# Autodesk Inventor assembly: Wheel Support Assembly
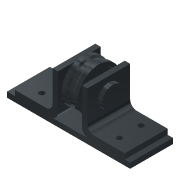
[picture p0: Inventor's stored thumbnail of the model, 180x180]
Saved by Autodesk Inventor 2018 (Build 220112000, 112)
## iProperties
Created: 2016-08
Part Number: Wheel Support Assembly
Document SubType Name: Assembly
Designer: Sandeep
Author: Sandeep
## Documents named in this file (5)
- E:\_Deepak\Inventor\Autodesk Inventor_2017_Project\Resources\Inventor_2018_tut\c15_Inv_tut_2018\c15_tut03_inv\Wheel Support Assembly.iam
- E:\_Deepak\Inventor\Autodesk Inventor_2017_Project\Resources\Inventor_2017_tut\c15_Inv_tut_2017\ch15_tut03\base.ipt
- E:\_Deepak\Inventor\Autodesk Inventor_2017_Project\Resources\Inventor_2017_tut\c15_Inv_tut_2017\ch15_tut03\Support.ipt
- E:\_Deepak\Inventor\Autodesk Inventor_2017_Project\Resources\Inventor_2017_tut\c15_Inv_tut_2017\ch15_tut03\Wheel.ipt
- E:\_Deepak\Inventor\Autodesk Inventor_2017_Project\Resources\Inventor_2017_tut\c15_Inv_tut_2017\ch15_tut03\Shoulder screw.ipt
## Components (5 placed, 4 different names)
1. base:1 — Insert:1, Mate:1, Insert:2, Mate:2
2. Support:1 — Insert:1, Mate:1, Insert:3
3. Support:2 — Insert:2, Mate:2, Mate:3, Mate:4
4. Wheel:1 — Insert:3
5. Shoulder screw:1 — Mate:3, Mate:4
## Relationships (7: Mate 4, Insert 3)
- Insert:1: base:1 ↔ Support:1
- Mate:1: base:1 ↔ Support:1
- Insert:2: base:1 ↔ Support:2
- Mate:2: base:1 ↔ Support:2
- Insert:3: Support:1 ↔ Wheel:1
- Mate:3: Support:2 ↔ Shoulder screw:1
- Mate:4: Support:2 ↔ Shoulder screw:1
